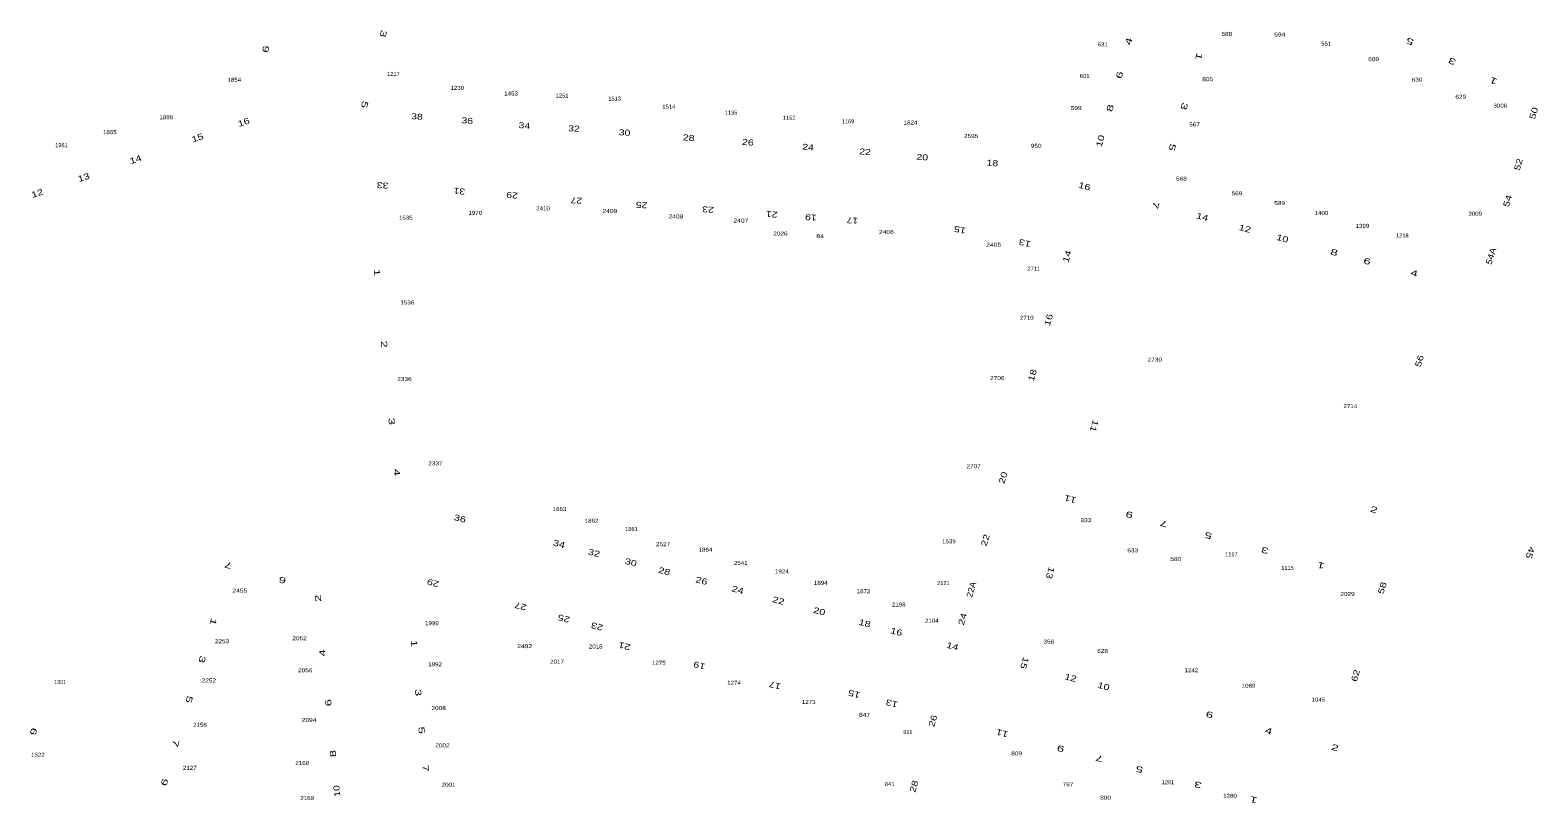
# Model space of a CAD drawing. Extents: x -828673 to -815583, y -1077737 to -1063807.
# Drawn here: x -823382.5 to -823006.8, y -1070658.8 to -1070466.4 of the extents above; entities that cross this region are included whole.
import ezdxf
from ezdxf.enums import TextEntityAlignment as Align

# ---------------------------------------------------------------- set-up
doc = ezdxf.new("R2010")
doc.units = 0
doc.header["$LTSCALE"] = 0.4
doc.layers.add('1', color=7, linetype='Continuous')
doc.layers.add('2', color=7, linetype='Continuous')

msp = doc.modelspace()

# ---------------------------------------------------------------- texts
at = {"layer": '1'}
for s, width, p in [('588', 1.2, (-823084.296, -1070467.817)), ('594', 1.25, (-823071.101, -1070467.973)), ('631', 1.1, (-823115.233, -1070470.427)), ('551', 1.1, (-823059.525, -1070470.238)), ('609', 1.2, (-823047.739, -1070474.116)), ('1854', 1.15, (-823331.668, -1070479.252)), ('1217', 1.05, (-823291.984, -1070477.771)), ('1230', 1.15, (-823276.088, -1070481.257)), ('601', 1.1, (-823119.731, -1070478.308)), ('805', 1.2, (-823089.073, -1070479.099)), ('630', 1.2, (-823036.893, -1070479.209)), ('1453', 1.15, (-823262.681, -1070482.666)), ('1251', 1.05, (-823249.956, -1070483.176)), ('1513', 1.05, (-823236.879, -1070483.92)), ('629', 1.2, (-823026.008, -1070483.479)), ('1889', 1.15, (-823348.625, -1070488.576)), ('1514', 1.1, (-823223.359, -1070485.95)), ('1135', 1.05, (-823207.855, -1070487.439)), ('1152', 1.05, (-823193.368, -1070488.692)), ('599', 1.2, (-823121.845, -1070486.299)), ('3008', 1.15, (-823016.14, -1070485.69)), ('1865', 1.15, (-823362.678, -1070492.295)), ('1169', 1.05, (-823178.711, -1070489.59)), ('1824', 1.15, (-823163.128, -1070489.903)), ('567', 1.2, (-823092.362, -1070490.381)), ('1961', 1.05, (-823374.746, -1070495.534)), ('2595', 1.2, (-823148.027, -1070493.269)), ('950', 1.2, (-823131.829, -1070495.701)), ('568', 1.2, (-823095.605, -1070503.887)), ('569', 1.2, (-823081.784, -1070507.531)), ('2410', 1.15, (-823254.71, -1070511.263)), ('589', 1.2, (-823071.133, -1070509.959)), ('1535', 1.15, (-823288.907, -1070513.609)), ('1970', 1.15, (-823271.601, -1070512.395)), ('2409', 1.25, (-823238.07, -1070511.929)), ('2408', 1.25, (-823221.586, -1070513.3)), ('2407', 1.25, (-823205.409, -1070514.312)), ('1400', 1.15, (-823060.718, -1070512.427)), ('3009', 1.15, (-823022.41, -1070512.6)), ('2026', 1.2, (-823195.542, -1070517.563)), ('84', 1.3, (-823185.65, -1070518.19)), ('2406', 1.25, (-823169.152, -1070517.171)), ('1399', 1.15, (-823050.516, -1070515.63)), ('1218', 1.05, (-823040.57, -1070518.019)), ('2405', 1.25, (-823142.407, -1070520.337)), ('2711', 1.05, (-823132.423, -1070526.291)), ('1536', 1.15, (-823288.516, -1070534.697)), ('2710', 1.15, (-823134.162, -1070538.527)), ('2730', 1.2, (-823102.247, -1070548.964)), ('2336', 1.2, (-823289.26, -1070553.788)), ('2706', 1.2, (-823141.507, -1070553.552)), ('2714', 1.15, (-823053.53, -1070560.543)), ('2337', 1.2, (-823281.546, -1070574.785)), ('2707', 1.2, (-823147.419, -1070575.528)), ('1863', 1.15, (-823250.611, -1070586.153)), ('1862', 1.15, (-823242.623, -1070589.091)), ('933', 1.2, (-823119.423, -1070588.941)), ('1861', 1.05, (-823232.678, -1070591.128)), ('2527', 1.2, (-823224.808, -1070594.927)), ('1864', 1.15, (-823214.237, -1070596.299)), ('1539', 1.15, (-823153.562, -1070594.208)), ('633', 1.2, (-823107.755, -1070596.462)), ('2541', 1.15, (-823205.427, -1070599.589)), ('580', 1.2, (-823097.026, -1070598.617)), ('1924', 1.15, (-823195.199, -1070601.689)), ('1894', 1.15, (-823185.489, -1070604.548)), ('2121', 1.05, (-823154.933, -1070604.628)), ('2455', 1.25, (-823330.289, -1070606.517)), ('1872', 1.15, (-823174.839, -1070606.625)), ('2029', 1.2, (-823054.22, -1070607.337)), ('2198', 1.15, (-823166.069, -1070609.954)), ('1999', 1.15, (-823282.412, -1070614.597)), ('2104', 1.15, (-823157.83, -1070613.99)), ('2253', 1.2, (-823334.723, -1070619.087)), ('2052', 1.2, (-823315.402, -1070618.347)), ('2492', 1.25, (-823259.285, -1070620.316)), ('358', 1.2, (-823128.659, -1070619.189)), ('2018', 1.15, (-823241.589, -1070620.414)), ('628', 1.2, (-823115.268, -1070621.5)), ('2056', 1.2, (-823313.977, -1070626.322)), ('1992', 1.15, (-823281.625, -1070624.828)), ('2017', 1.15, (-823251.238, -1070624.192)), ('1275', 1.15, (-823225.857, -1070624.454)), ('1242', 1.15, (-823093.145, -1070626.318)), ('1321', 1.05, (-823375.089, -1070629.249)), ('2252', 1.2, (-823337.99, -1070628.871)), ('1274', 1.15, (-823207.136, -1070629.438)), ('1089', 1.15, (-823078.883, -1070630.19)), ('1273', 1.15, (-823188.519, -1070634.213)), ('1045', 1.15, (-823061.498, -1070633.637)), ('2094', 1.25, (-823313.034, -1070638.699)), ('2008', 1.2, (-823280.732, -1070635.754)), ('847', 1.25, (-823174.597, -1070637.432)), ('2156', 1.15, (-823340.208, -1070639.91)), ('2002', 1.2, (-823279.788, -1070645.041)), ('1322', 1.15, (-823380.613, -1070647.358)), ('2168', 1.15, (-823314.723, -1070649.421)), ('809', 1.2, (-823136.675, -1070647.04)), ('2127', 1.15, (-823342.742, -1070650.631)), ('1281', 1.05, (-823098.979, -1070654.21)), ('2001', 1.15, (-823278.269, -1070654.833)), ('841', 1.1, (-823168.304, -1070654.641)), ('797', 1.2, (-823123.88, -1070654.737)), ('1280', 1.15, (-823083.494, -1070657.596)), ('2169', 1.15, (-823313.509, -1070658.135)), ('800', 1.2, (-823114.527, -1070658.059))]:
    msp.add_text(s, height=1, dxfattribs=dict(at, width=width)).set_placement(p, align=Align.CENTER)
for s, p in [('1117', (-823083.166, -1070597.442)), ('1115', (-823069.177, -1070600.834)), ('911', (-823163.795, -1070641.735))]:
    msp.add_text(s, height=1, dxfattribs=at).set_placement(p, align=Align.CENTER)
at = {"layer": '2'}
for s, rotation, width, p in [('3', 255.324, 1.65, (-823295.2268, -1070467.0765)), ('4', 74.544, 1.65, (-823108.0288, -1070469.3789)), ('5', 154.945, 1.7, (-823038.3569, -1070468.5178)), ('6', 75.508, 1.65, (-823323.1162, -1070471.3012)), ('1', 254.186, 1.65, (-823091.963, -1070472.7131)), ('3', 155.03, 1.7, (-823027.8244, -1070473.4551)), ('6', 73.807, 1.65, (-823110.329, -1070477.7692)), ('1', 155.508, 1.65, (-823017.5461, -1070478.3125)), ('5', 255.355, 1.65, (-823299.8862, -1070484.7354)), ('38', 355.887, 1.3, (-823286.1843, -1070488.6405)), ('8', 74.003, 1.65, (-823112.6802, -1070485.9957)), ('3', 254.077, 1.65, (-823095.6147, -1070485.1227)), ('50', 72.881, 1.35, (-823007.1226, -1070487.2868)), ('16', 18.558, 1.35, (-823329.0872, -1070490.026)), ('36', 355.396, 1.3, (-823273.6547, -1070489.6632)), ('34', 354.962, 1.3, (-823259.4249, -1070490.8775)), ('32', 355.794, 1.3, (-823247.0535, -1070491.6179)), ('30', 355.941, 1.3, (-823234.4466, -1070492.6351)), ('15', 19.091, 1.35, (-823340.5938, -1070493.8924)), ('28', 355.201, 1.3, (-823218.4797, -1070493.9253)), ('26', 355.605, 1.3, (-823203.721, -1070495.0587)), ('24', 355.184, 1.3, (-823188.7255, -1070496.2737)), ('10', 74.231, 1.35, (-823115.1232, -1070494.1758)), ('5', 253.648, 1.65, (-823098.5935, -1070495.3463)), ('14', 19.274, 1.35, (-823356.0191, -1070499.2998)), ('22', 355.186, 1.3, (-823174.5194, -1070497.4177)), ('20', 355.455, 1.3, (-823160.2579, -1070498.7657)), ('18', 355.262, 1.3, (-823142.7795, -1070500.2057)), ('52', 72.902, 1.35, (-823010.9143, -1070500.062)), ('13', 19.114, 1.35, (-823368.9611, -1070503.7759)), ('12', 18.713, 1.35, (-823380.5351, -1070507.723)), ('33', 175.784, 1.3, (-823294.6299, -1070504.3038)), ('31', 174.839, 1.3, (-823275.502, -1070505.7653)), ('16', 344.843, 1.35, (-823119.9676, -1070505.9841)), ('29', 175.691, 1.3, (-823262.3667, -1070506.7784)), ('27', 176.022, 1.3, (-823246.3515, -1070508.072)), ('25', 175.834, 1.3, (-823230.1025, -1070509.2072)), ('23', 175.822, 1.3, (-823213.5359, -1070510.3368)), ('7', 253.711, 1.65, (-823102.7315, -1070509.7596)), ('54', 72.902, 1.35, (-823013.6343, -1070509.128)), ('21', 175.01, 1.3, (-823197.6558, -1070511.5248)), ('19', 176.142, 1.3, (-823187.9065, -1070512.2792)), ('17', 175.512, 1.3, (-823177.5703, -1070513.0568)), ('14', 345.325, 1.35, (-823090.5885, -1070513.6248)), ('15', 168.869, 1.35, (-823150.6712, -1070515.3785)), ('12', 344.851, 1.35, (-823079.9785, -1070516.5269)), ('10', 345.045, 1.35, (-823070.62, -1070518.993)), ('13', 165.232, 1.35, (-823134.4578, -1070518.7058)), ('14', 73.952, 1.35, (-823123.389, -1070522.9563)), ('8', 345.089, 1.65, (-823057.75, -1070522.4506)), ('54A', 72.882, 1.2, (-823017.7545, -1070522.8923)), ('6', 345.353, 1.65, (-823049.5276, -1070524.6813)), ('1', 275.571, 1.6, (-823296.8283, -1070526.8197)), ('4', 345.387, 1.65, (-823037.7982, -1070527.6498)), ('16', 73.923, 1.35, (-823128.0082, -1070538.7432)), ('2', 275.544, 1.6, (-823295.0537, -1070544.6775)), ('56', 72.886, 1.35, (-823035.5947, -1070548.9977)), ('18', 74.187, 1.35, (-823132.045, -1070552.5359)), ('3', 275.69, 1.6, (-823293.1714, -1070563.8866)), ('11', 253.291, 1.35, (-823118.0479, -1070564.7529)), ('4', 275.663, 1.6, (-823291.9198, -1070576.5785)), ('20', 74.108, 1.35, (-823139.356, -1070578.0774)), ('11', 165.1, 1.35, (-823123.1121, -1070582.4724)), ('2', 343.018, 1.65, (-823047.8615, -1070586.5256)), ('36', 345.383, 1.35, (-823275.5923, -1070588.7514)), ('9', 165.696, 1.65, (-823108.4122, -1070586.3262)), ('7', 165.014, 1.65, (-823099.8366, -1070588.5923)), ('22', 73.69, 1.35, (-823143.7754, -1070593.6321)), ('5', 165.276, 1.65, (-823088.7169, -1070591.5326)), ('34', 345.387, 1.35, (-823250.9112, -1070595.0833)), ('32', 345.707, 1.35, (-823242.1797, -1070597.314)), ('3', 165.471, 1.65, (-823074.6108, -1070595.2406)), ('45', 252.796, 1.35, (-823009.3837, -1070596.3072)), ('7', 163.949, 1.65, (-823332.9796, -1070598.9492)), ('30', 345.057, 1.35, (-823233.0189, -1070599.6687)), ('28', 345.415, 1.35, (-823224.6634, -1070601.8934)), ('13', 253.745, 1.35, (-823129.0073, -1070601.3566)), ('1', 164.843, 1.65, (-823060.6424, -1070599.0075)), ('6', 163.382, 1.65, (-823319.4655, -1070602.6942)), ('29', 165.089, 1.35, (-823281.94, -1070603.3522)), ('26', 345.964, 1.35, (-823215.3834, -1070604.2414)), ('22A', 74.206, 1.1, (-823147.2589, -1070605.9211)), ('58', 73.04, 1.35, (-823044.8595, -1070605.5443)), ('2', 95.059, 1.6, (-823310.0545, -1070607.8381)), ('24', 344.831, 1.35, (-823206.3782, -1070606.5145)), ('22', 345.3, 1.35, (-823196.2288, -1070609.2014)), ('27', 165.012, 1.35, (-823260.125, -1070609.1751)), ('20', 345.306, 1.35, (-823186.0487, -1070611.8633)), ('24', 73.865, 1.35, (-823149.4547, -1070613.2954)), ('1', 253.529, 1.65, (-823337.6115, -1070613.5184)), ('25', 165.831, 1.35, (-823249.3509, -1070612.2152)), ('23', 165.379, 1.35, (-823241.0657, -1070614.2076)), ('18', 345.498, 1.35, (-823174.7218, -1070614.8254)), ('16', 345.589, 1.35, (-823166.8142, -1070616.9401)), ('1', 275.955, 1.6, (-823287.5862, -1070619.2072)), ('21', 165.651, 1.35, (-823234.2321, -1070619.0785)), ('14', 345.22, 1.35, (-823152.8593, -1070620.5485)), ('3', 253.505, 1.65, (-823340.3909, -1070622.8881)), ('4', 95.784, 1.6, (-823308.9581, -1070621.4301)), ('15', 254.021, 1.35, (-823135.4214, -1070623.8085)), ('19', 165.117, 1.35, (-823215.5614, -1070623.8988)), ('12', 345.365, 1.35, (-823123.4135, -1070628.4098)), ('62', 73.593, 1.35, (-823051.5098, -1070627.3633)), ('3', 275.356, 1.6, (-823286.5667, -1070631.4405)), ('17', 165.252, 1.35, (-823196.7361, -1070628.8853)), ('10', 345.308, 1.35, (-823115.1897, -1070630.5253)), ('5', 253.503, 1.65, (-823343.6059, -1070632.884)), ('6', 95.564, 1.6, (-823307.4796, -1070633.8407)), ('15', 165.82, 1.35, (-823176.9933, -1070631.0078)), ('13', 165.236, 1.35, (-823167.6059, -1070633.3639)), ('26', 73.413, 1.35, (-823156.8462, -1070638.6396)), ('6', 345.128, 1.65, (-823088.807, -1070637.5939)), ('6', 253.509, 1.65, (-823382.4098, -1070640.8701)), ('5', 275.384, 1.6, (-823285.7273, -1070640.8451)), ('11', 165.734, 1.35, (-823140.1012, -1070640.7728)), ('4', 345.26, 1.65, (-823074.0738, -1070641.6618)), ('7', 253.582, 1.65, (-823346.9825, -1070643.817)), ('9', 165.138, 1.65, (-823125.5181, -1070644.6182)), ('2', 345.163, 1.65, (-823057.5511, -1070645.8143)), ('8', 95.553, 1.6, (-823306.3174, -1070646.5156)), ('7', 275.867, 1.6, (-823284.7266, -1070650.2893)), ('7', 165.282, 1.65, (-823115.88, -1070647.0917)), ('9', 253.273, 1.65, (-823349.7835, -1070653.4811)), ('5', 165.149, 1.65, (-823105.8798, -1070649.8035)), ('10', 95.814, 1.3, (-823305.3796, -1070655.83)), ('28', 74.318, 1.35, (-823161.5714, -1070654.9562)), ('3', 165.111, 1.65, (-823091.2858, -1070653.6358)), ('1', 165.161, 1.65, (-823077.3999, -1070657.3796))]:
    msp.add_text(s, height=1.5, rotation=rotation, dxfattribs=dict(at, width=width)).set_placement(p, align=Align.CENTER)

doc.saveas('drawing.dxf')
